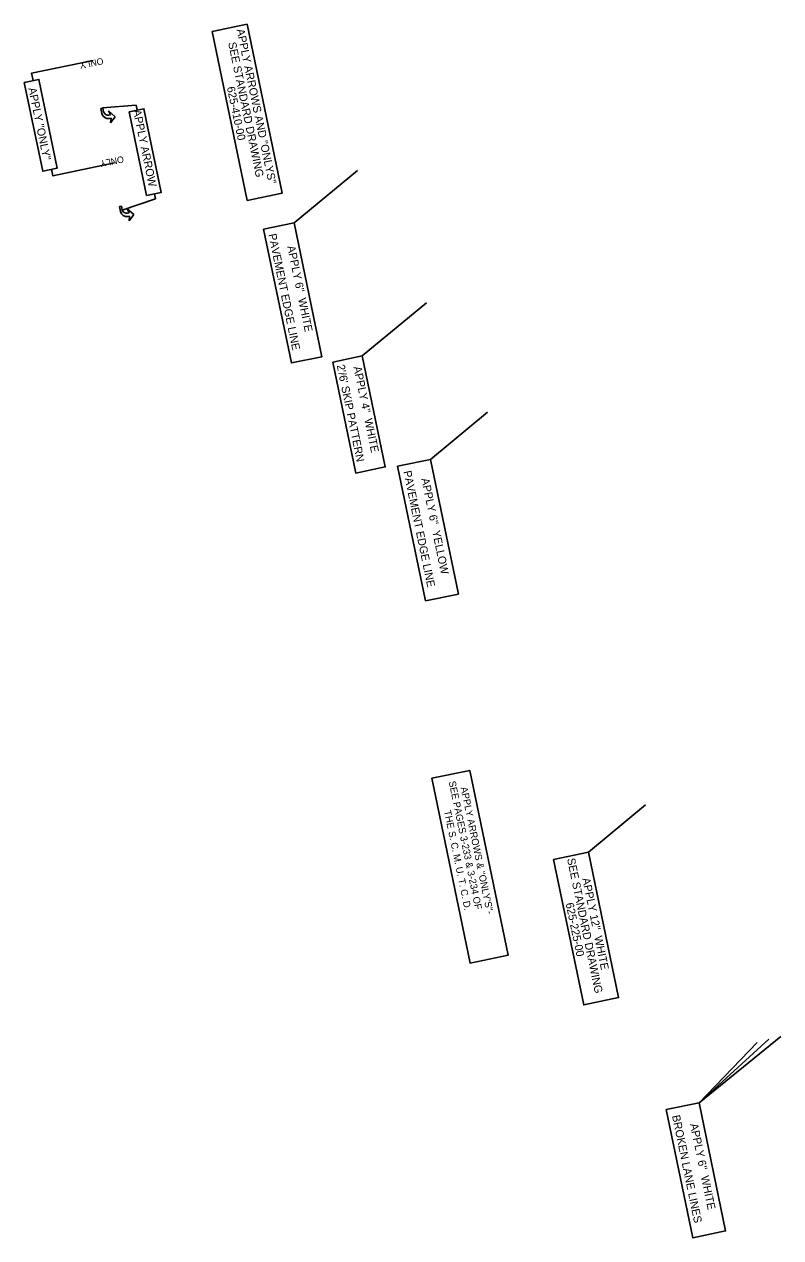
# Model space of a CAD drawing. Extents: x 1966013 to 1974896, y 789499 to 804826.
# Drawn here: x 1966986 to 1967742, y 789499 to 790712 of the extents above; entities that cross this region are included whole.
import ezdxf

# ---------------------------------------------------------------- set-up
doc = ezdxf.new("R2010")
doc.units = 0
doc.layers.add('RD_EX_H2O_BlueLn', color=7, linetype='Continuous')
doc.layers.add('RD_PD_ALT5_CL', color=7, linetype='Continuous')

msp = doc.modelspace()

# ---------------------------------------------------------------- linework, layer by layer
at = {"layer": 'RD_EX_H2O_BlueLn'}
for p, q in [((1967256, 790513.6), (1967319.4, 790566.1)), ((1967324.2, 790380.6), (1967388.3, 790433.6)), ((1967392.3, 790277), (1967449.3, 790324.2)), ((1967550.2, 789884.4), (1967607.2, 789931.6)), ((1967660.8, 789633.7), (1967742.4, 789699.9)), ((1967660.8, 789633.7), (1967730.4, 789697.5)), ((1967660.8, 789633.7), (1967718.9, 789694.2))]:
    msp.add_line(p, q, dxfattribs=at)
for points in [[(1967174.3, 790705), (1967209.3, 790536.1), (1967244.1, 790543.3), (1967209.1, 790712.2)], [(1966986.4, 790654.1), (1967004.8, 790565.3), (1967019.4, 790568.4), (1967001, 790657.1)], [(1967091.2, 790624.8), (1967108.6, 790541.1), (1967123.2, 790544.1), (1967105.9, 790627.8)], [(1967225.5, 790507.3), (1967253.3, 790373.5), (1967283.8, 790379.8), (1967256, 790513.6)], [(1967294.7, 790374.4), (1967317.7, 790263.5), (1967347.2, 790269.6), (1967324.2, 790380.6)], [(1967359.5, 790270.2), (1967387.4, 790135.7), (1967420.2, 790142.5), (1967392.3, 790277)], [(1967393.6, 789958.2), (1967431.9, 789773.4), (1967469.9, 789781.3), (1967431.6, 789966.1)], [(1967515.4, 789877.1), (1967545.5, 789731.7), (1967580.3, 789738.9), (1967550.2, 789884.4)], [(1967628, 789626.9), (1967654.5, 789498.8), (1967687.3, 789505.6), (1967660.8, 789633.7)]]:
    msp.add_lwpolyline(points, close=True, dxfattribs=at)
for points in [[(1966995.2, 790655.9), (1966993.7, 790663.4), (1967055.3, 790675.9)], [(1967099.1, 790626.3), (1967098.1, 790631.3), (1967064.6, 790628.6)], [(1967013.6, 790567.2), (1967015, 790560.5), (1967076.5, 790573.5)], [(1967116.4, 790542.7), (1967117.5, 790537.7), (1967084.1, 790526.4)]]:
    msp.add_lwpolyline(points, dxfattribs=at)
at = {"layer": 'RD_PD_ALT5_CL'}
for p, q in [((1967064.9, 790628.3), (1967063, 790627.9)), ((1967063, 790627.9), (1967064, 790623)), ((1967065.7, 790624.7), (1967064.9, 790628.3)), ((1967077.2, 790619.8), (1967070.7, 790625.8)), ((1967070.7, 790625.8), (1967072.5, 790621.6)), ((1967072.5, 790621.6), (1967071, 790621.3)), ((1967071.7, 790618), (1967073.1, 790618.3)), ((1967072.6, 790613.6), (1967077.2, 790619.8)), ((1967073.1, 790618.3), (1967072.6, 790613.6)), ((1967083.5, 790530.4), (1967081.6, 790530)), ((1967081.6, 790530), (1967082.6, 790525.1)), ((1967084.3, 790526.8), (1967083.5, 790530.4)), ((1967095.8, 790521.9), (1967089.3, 790527.8)), ((1967089.3, 790527.8), (1967091.1, 790523.6)), ((1967091.1, 790523.6), (1967089.6, 790523.3)), ((1967090.3, 790520), (1967091.7, 790520.3)), ((1967091.2, 790515.6), (1967095.8, 790521.9)), ((1967091.7, 790520.3), (1967091.2, 790515.6))]:
    msp.add_line(p, q, dxfattribs=at)
for centre, radius in [((1967070.3, 790624.4), 6.5), ((1967070.1, 790625.7), 4.5), ((1967088.9, 790526.4), 6.5), ((1967088.7, 790527.7), 4.5)]:
    msp.add_arc(centre, radius, 191.7116, 281.7116, dxfattribs=at)

# ---------------------------------------------------------------- texts
at = {"layer": 'RD_EX_H2O_BlueLn'}
for s, height, rotation, p in [('APPLY ARROWS AND "ONLYS"', 8, 281.7118, (1967198.5, 790706.8)), ('SEE STANDARD DRAWING', 8, 281.7118, (1967190.1, 790693.6)), ('APPLY "ONLY"', 7.999, 281.6981, (1966990.4, 790648.1)), ('625-410-00 ', 8, 281.7118, (1967188.8, 790649.1)), ('APPLY ARROW', 7.999, 281.6981, (1967095, 790626)), ('PAVEMENT EDGE LINE', 8, 281.7118, (1967230.3, 790502)), ("APPLY 6''  WHITE", 8, 281.7118, (1967249.1, 790490)), ("2'/6' SKIP PATTERN", 7.999, 281.712, (1967298.6, 790371.1)), ("APPLY 4''  WHITE", 7.999, 281.712, (1967315.3, 790369.4)), ('PAVEMENT EDGE LINE', 8, 281.7118, (1967365.2, 790265)), ("APPLY 6''  YELLOW", 8, 281.7118, (1967383.1, 790257.6)), ('SEE PAGES 3-233 & 3-234 OF', 7, 281.698, (1967410.5, 789954.8)), ('APPLY ARROWS & "ONLY\'S"-', 7, 281.698, (1967422.4, 789948.9)), ('THE S. C. M. U. T. C. D.', 7, 281.698, (1967405.8, 789925.5)), ('SEE STANDARD DRAWING', 8, 281.7118, (1967528.8, 789877.6)), ("APPLY 12''  WHITE", 8, 281.7118, (1967543.9, 789857.9)), ('625-225-00', 8, 281.7118, (1967527.4, 789833)), ('BROKEN LANE LINES', 8, 281.7118, (1967633.7, 789620.7)), ("APPLY 6''  WHITE", 8, 281.7118, (1967651.7, 789612.3))]:
    msp.add_text(s, height=height, rotation=rotation, dxfattribs=at).set_placement(p)
at = {"layer": 'RD_PD_ALT5_CL'}
for p in [(1967064.7, 790678.8), (1967085.1, 790580.6)]:
    msp.add_text('ONLY', height=6.56, rotation=191.7116, dxfattribs=at).set_placement(p)

doc.saveas('drawing.dxf')
